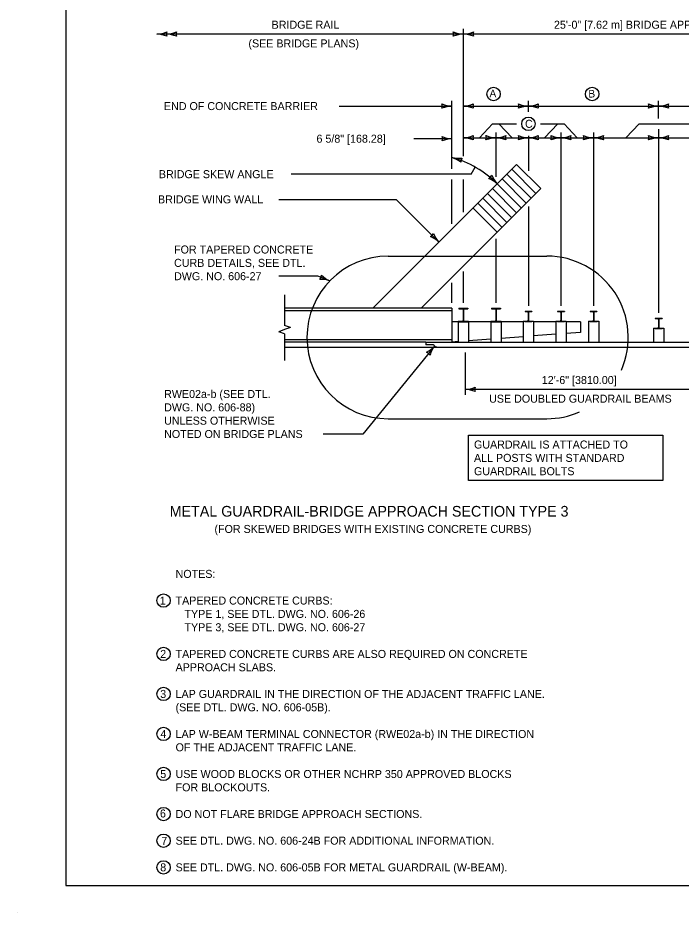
# Model space of a CAD drawing. Extents: x 49991.4 to 50021, y 49987.6 to 50011.4.
# Drawn here: x 49999.98 to 50004.95, y 49999.86 to 50006.57 of the extents above; entities that cross this region are included whole.
import ezdxf

# ---------------------------------------------------------------- set-up
doc = ezdxf.new("R2010")
doc.units = 0
for name, color, linetype in [('Level 1', 7, 'Continuous'), ('Level 2', 7, 'Continuous'), ('Level 3', 7, 'Continuous'), ('Level 4', 7, 'Continuous'), ('Level 6', 7, 'Continuous')]:
    doc.layers.add(name, color=color, linetype=linetype)

msp = doc.modelspace()

# ---------------------------------------------------------------- linework, layer by layer
at = {"layer": 'Level 1'}
for p, q in [((50002.638, 50004.3895), (50003.7157, 50005.4673)), ((50003.8609, 50005.2494), (50003.6793, 50005.431)), ((50003.8973, 50005.2857), (50003.7157, 50005.4673)), ((50003.7883, 50005.1768), (50003.6067, 50005.3583)), ((50003.8246, 50005.2131), (50003.643, 50005.3947)), ((50003.0012, 50004.3895), (50003.8973, 50005.2857)), ((50003.7157, 50005.1041), (50003.5341, 50005.2857)), ((50003.752, 50005.1404), (50003.5704, 50005.322)), ((50003.643, 50005.0315), (50003.4614, 50005.2131)), ((50003.6793, 50005.0678), (50003.4977, 50005.2494)), ((50003.5704, 50004.9588), (50003.3888, 50005.1404)), ((50003.6067, 50004.9952), (50003.4251, 50005.1767)), ((50003.2304, 50004.3895), (50001.9766, 50004.3895)), ((50003.2304, 50004.3705), (50001.9766, 50004.3705)), ((50003.2304, 50004.3895), (50003.2304, 50004.1359)), ((50003.2823, 50004.3909), (50003.3509, 50004.3909)), ((50003.2823, 50004.3909), (50003.2823, 50004.3857)), ((50003.2823, 50004.3857), (50003.3104, 50004.3857)), ((50003.315, 50004.3811), (50003.315, 50004.2965)), ((50003.3182, 50004.3811), (50003.3182, 50004.2965)), ((50003.3228, 50004.3857), (50003.3509, 50004.3857)), ((50003.3509, 50004.3909), (50003.3509, 50004.3857)), ((50003.5263, 50004.3909), (50003.5948, 50004.3909)), ((50003.5263, 50004.3909), (50003.5263, 50004.3857)), ((50003.5263, 50004.3857), (50003.5544, 50004.3857)), ((50003.5589, 50004.3811), (50003.5589, 50004.2965)), ((50003.5622, 50004.3811), (50003.5622, 50004.2965)), ((50003.5667, 50004.3857), (50003.5948, 50004.3857)), ((50003.5948, 50004.3909), (50003.5948, 50004.3857)), ((50003.7789, 50004.3673), (50003.8302, 50004.3673)), ((50003.7789, 50004.3673), (50003.7789, 50004.3645)), ((50003.7789, 50004.3645), (50003.7965, 50004.3645)), ((50003.8034, 50004.3575), (50003.8034, 50004.2989)), ((50003.8056, 50004.3575), (50003.8056, 50004.2989)), ((50003.8126, 50004.3645), (50003.8302, 50004.3645)), ((50003.8302, 50004.3673), (50003.8302, 50004.3645)), ((50004.0229, 50004.3673), (50004.0742, 50004.3673)), ((50004.0229, 50004.3673), (50004.0229, 50004.3645)), ((50004.0229, 50004.3645), (50004.0405, 50004.3645)), ((50004.0474, 50004.3575), (50004.0474, 50004.2989)), ((50004.0496, 50004.3575), (50004.0496, 50004.2989)), ((50004.0566, 50004.3645), (50004.0742, 50004.3645)), ((50004.0742, 50004.3673), (50004.0742, 50004.3645)), ((50004.2669, 50004.3673), (50004.3182, 50004.3673)), ((50004.2669, 50004.3673), (50004.2669, 50004.3645)), ((50004.2669, 50004.3645), (50004.2845, 50004.3645)), ((50004.2914, 50004.3575), (50004.2914, 50004.2989)), ((50004.2936, 50004.3575), (50004.2936, 50004.2989)), ((50004.3006, 50004.3645), (50004.3182, 50004.3645)), ((50004.3182, 50004.3673), (50004.3182, 50004.3645)), ((50003.2776, 50004.2868), (50003.2304, 50004.2868)), ((50003.2776, 50004.292), (50003.2817, 50004.292)), ((50003.2776, 50004.292), (50003.2776, 50004.1359)), ((50003.2817, 50004.2868), (50003.2817, 50004.292)), ((50003.2817, 50004.2868), (50003.2823, 50004.2868)), ((50003.2823, 50004.2868), (50003.2823, 50004.292)), ((50003.2823, 50004.292), (50003.3104, 50004.292)), ((50003.2823, 50004.2868), (50003.3509, 50004.2868)), ((50003.3228, 50004.292), (50003.3509, 50004.292)), ((50003.3509, 50004.2868), (50003.3509, 50004.292)), ((50003.3515, 50004.2868), (50003.3509, 50004.2868)), ((50003.3515, 50004.2868), (50003.3515, 50004.292)), ((50003.3515, 50004.292), (50003.3556, 50004.292)), ((50003.3556, 50004.292), (50003.3556, 50004.1359)), ((50003.5215, 50004.2868), (50003.3556, 50004.2868)), ((50003.5215, 50004.292), (50003.5256, 50004.292)), ((50003.5215, 50004.292), (50003.5215, 50004.1359)), ((50003.5256, 50004.2868), (50003.5256, 50004.292)), ((50003.5256, 50004.2868), (50003.5263, 50004.2868)), ((50003.5263, 50004.2868), (50003.5263, 50004.292)), ((50003.5263, 50004.292), (50003.5544, 50004.292)), ((50003.5263, 50004.2868), (50003.5948, 50004.2868)), ((50003.5667, 50004.292), (50003.5948, 50004.292)), ((50003.5948, 50004.2868), (50003.5948, 50004.292)), ((50003.5948, 50004.2868), (50003.5955, 50004.2868)), ((50003.5955, 50004.2868), (50003.5955, 50004.292)), ((50003.5955, 50004.292), (50003.5996, 50004.292)), ((50003.5996, 50004.292), (50003.5996, 50004.1359)), ((50003.7655, 50004.2868), (50003.5996, 50004.2868)), ((50003.7655, 50004.292), (50003.7783, 50004.292)), ((50003.7655, 50004.292), (50003.7655, 50004.1359)), ((50003.7783, 50004.2892), (50003.7783, 50004.292)), ((50003.7783, 50004.2892), (50003.7789, 50004.2892)), ((50003.7789, 50004.2892), (50003.7789, 50004.292)), ((50003.7789, 50004.292), (50003.7965, 50004.292)), ((50003.7789, 50004.2892), (50003.8302, 50004.2892)), ((50003.8126, 50004.292), (50003.8302, 50004.292)), ((50003.8302, 50004.2892), (50003.8302, 50004.292)), ((50003.8308, 50004.2892), (50003.8302, 50004.2892)), ((50003.8308, 50004.2892), (50003.8308, 50004.292)), ((50003.8308, 50004.292), (50003.8436, 50004.292)), ((50003.8436, 50004.292), (50003.8436, 50004.1359)), ((50004.0095, 50004.2868), (50003.8436, 50004.2868)), ((50004.0095, 50004.292), (50004.0222, 50004.292)), ((50004.0095, 50004.292), (50004.0095, 50004.1359)), ((50004.0222, 50004.2892), (50004.0222, 50004.292)), ((50004.0222, 50004.2892), (50004.0229, 50004.2892)), ((50004.0229, 50004.2892), (50004.0229, 50004.292)), ((50004.0229, 50004.292), (50004.0405, 50004.292)), ((50004.0229, 50004.2892), (50004.0742, 50004.2892)), ((50004.0566, 50004.292), (50004.0742, 50004.292)), ((50004.0742, 50004.2892), (50004.0742, 50004.292)), ((50004.0742, 50004.2892), (50004.0748, 50004.2892)), ((50004.0748, 50004.2892), (50004.0748, 50004.292)), ((50004.0748, 50004.292), (50004.0876, 50004.292)), ((50004.0876, 50004.292), (50004.0876, 50004.1359)), ((50004.1957, 50004.2868), (50004.0876, 50004.2868)), ((50004.1957, 50004.2868), (50004.1957, 50004.2074)), ((50004.2535, 50004.292), (50004.2535, 50004.1359)), ((50004.2535, 50004.292), (50004.2662, 50004.292)), ((50004.2662, 50004.2892), (50004.2662, 50004.292)), ((50004.2662, 50004.2892), (50004.3188, 50004.2892)), ((50004.2669, 50004.2892), (50004.2669, 50004.292)), ((50004.2669, 50004.292), (50004.2845, 50004.292)), ((50004.3006, 50004.292), (50004.3182, 50004.292)), ((50004.3182, 50004.2892), (50004.3182, 50004.292)), ((50004.3188, 50004.2892), (50004.3188, 50004.292)), ((50004.3188, 50004.292), (50004.3316, 50004.292)), ((50004.3316, 50004.292), (50004.3316, 50004.1359)), ((50004.7548, 50004.3152), (50004.8061, 50004.3152)), ((50004.7548, 50004.3152), (50004.7548, 50004.3124)), ((50004.7548, 50004.3124), (50004.7724, 50004.3124)), ((50004.7793, 50004.3054), (50004.7793, 50004.2469)), ((50004.7816, 50004.3054), (50004.7816, 50004.2469)), ((50004.7885, 50004.3124), (50004.8061, 50004.3124)), ((50004.8061, 50004.3152), (50004.8061, 50004.3124)), ((50004.1957, 50004.2074), (50004.0876, 50004.1994)), ((50004.7414, 50004.2399), (50004.7414, 50004.1359)), ((50004.7414, 50004.2399), (50004.7542, 50004.2399)), ((50004.7542, 50004.2371), (50004.7542, 50004.2399)), ((50004.7542, 50004.2371), (50004.8067, 50004.2371)), ((50004.7548, 50004.2371), (50004.7548, 50004.2399)), ((50004.7548, 50004.2399), (50004.7724, 50004.2399)), ((50004.7885, 50004.2399), (50004.8061, 50004.2399)), ((50004.8061, 50004.2371), (50004.8061, 50004.2399)), ((50004.8067, 50004.2371), (50004.8067, 50004.2399)), ((50004.8067, 50004.2399), (50004.8195, 50004.2399)), ((50004.8195, 50004.2399), (50004.8195, 50004.1359)), ((50003.2304, 50004.1511), (50001.9767, 50004.1511)), ((50003.0353, 50004.1359), (50001.9767, 50004.1359)), ((50003.0353, 50004.1359), (50003.0353, 50004.1156)), ((50003.0353, 50004.1359), (50007.507, 50004.1359)), ((50003.2776, 50004.1394), (50003.2304, 50004.1359)), ((50003.5215, 50004.1574), (50003.3556, 50004.1451)), ((50003.7655, 50004.1755), (50003.5996, 50004.1632)), ((50004.0095, 50004.1936), (50003.8436, 50004.1813)), ((50001.9767, 50004.0968), (50007.507, 50004.0968)), ((50003.0695, 50004.1156), (50003.0353, 50004.1156)), ((49999.9766, 49999.8624), (49999.9766, 49999.8624))]:
    msp.add_line(p, q, dxfattribs=at)
msp.add_lwpolyline([(50008.6146, 50011.2628), (50000.3356, 50011.2628), (50000.3356, 50000.0624), (50008.6146, 50000.0624)], close=True, dxfattribs=at)
for centre, radius, start, end in [((50003.3104, 50004.3811), 0.00455, 0, 90), ((50003.3228, 50004.3811), 0.00455, 90, 180), ((50003.5544, 50004.3811), 0.00455, 0, 90), ((50003.5667, 50004.3811), 0.00455, 90, 180), ((50003.7965, 50004.3575), 0.00696, 0, 90), ((50003.8126, 50004.3575), 0.00696, 90, 180), ((50004.0405, 50004.3575), 0.00696, 0, 90), ((50004.0566, 50004.3575), 0.00696, 90, 180), ((50004.2845, 50004.3575), 0.00696, 0, 90), ((50004.3006, 50004.3575), 0.00696, 90, 180), ((50003.3104, 50004.2965), 0.00455, 270, 0), ((50003.3228, 50004.2965), 0.00455, 180, 270), ((50003.5544, 50004.2965), 0.00455, 270, 0), ((50003.5667, 50004.2965), 0.00455, 180, 270), ((50003.7965, 50004.2989), 0.00696, 270, 0), ((50003.8126, 50004.2989), 0.00696, 180, 270), ((50004.0405, 50004.2989), 0.00696, 270, 0), ((50004.0566, 50004.2989), 0.00696, 180, 270), ((50004.2845, 50004.2989), 0.00696, 270, 0), ((50004.3006, 50004.2989), 0.00696, 180, 270), ((50004.7724, 50004.3054), 0.00696, 0, 90), ((50004.7885, 50004.3054), 0.00696, 90, 180), ((50004.7724, 50004.2469), 0.00696, 270, 0), ((50004.7885, 50004.2469), 0.00696, 180, 270)]:
    msp.add_arc(centre, radius, start, end, dxfattribs=at)
msp.add_spline([(50003.1175, 50004.0968), (50003.1118, 50004.0985), (50003.1058, 50004.1026), (50003.1007, 50004.1085), (50003.0968, 50004.1125), (50003.0876, 50004.1146), (50003.0695, 50004.1156)], degree=3, dxfattribs=at)
at = {"layer": 'Level 2'}
msp.add_lwpolyline([(50003.3561, 50003.4373), (50004.8112, 50003.4373), (50004.8112, 50003.0973), (50003.3561, 50003.0973)], close=True, dxfattribs=at)
for centre, radius in [((50003.5429, 50005.995), 0.0504), ((50004.2824, 50005.995), 0.0504), ((50003.8043, 50005.7717), 0.0505), ((50001.0689, 50002.1978), 0.05), ((50001.0689, 50001.7978), 0.05), ((50001.0689, 50001.4978), 0.05), ((50001.0689, 50001.1978), 0.05), ((50001.0689, 50000.8978), 0.05), ((50001.0689, 50000.5978), 0.05), ((50001.0689, 50000.3978), 0.05), ((50001.0689, 50000.1978), 0.05)]:
    msp.add_circle(centre, radius, dxfattribs=at)
at = {"layer": 'Level 3'}
for p, q in [((50003.3166, 50005.5298), (50003.3166, 50006.4845)), ((50003.3166, 50006.4445), (50001.0189, 50006.4445)), ((50007.2182, 50006.4445), (50003.3166, 50006.4445)), ((50003.2304, 50005.4342), (50003.2304, 50005.9446)), ((50003.8043, 50005.8622), (50003.8043, 50005.9446)), ((50004.7798, 50005.8117), (50004.7798, 50005.9446)), ((50002.3862, 50005.9046), (50003.2304, 50005.9046)), ((50003.3166, 50005.9046), (50003.8043, 50005.9046)), ((50003.8043, 50005.9046), (50004.7798, 50005.9046)), ((50004.7798, 50005.9046), (50007.2182, 50005.9046)), ((50003.536, 50005.7717), (50003.4377, 50005.6672)), ((50003.536, 50005.7717), (50003.7138, 50005.7717)), ((50003.5833, 50005.7717), (50003.6816, 50005.6672)), ((50003.8947, 50005.7717), (50004.0716, 50005.7717)), ((50004.0243, 50005.7717), (50003.926, 50005.6672)), ((50004.0716, 50005.7717), (50004.1698, 50005.6672)), ((50004.634, 50005.7717), (50004.5358, 50005.6672)), ((50004.634, 50005.7717), (50005.6646, 50005.7717)), ((50003.5604, 50005.7072), (50003.5604, 50005.3736)), ((50003.8043, 50005.6813), (50003.8043, 50005.4187)), ((50004.0481, 50005.7072), (50004.0481, 50004.4073)), ((50004.292, 50005.7072), (50004.292, 50004.4073)), ((50004.7797, 50005.7317), (50004.7797, 50004.3552)), ((50003.2304, 50005.66), (50002.9452, 50005.66)), ((50003.3166, 50005.6672), (50003.5604, 50005.6672)), ((50003.5604, 50005.6672), (50003.8043, 50005.6672)), ((50003.8043, 50005.6672), (50004.0481, 50005.6672)), ((50004.0481, 50005.6672), (50004.292, 50005.6672)), ((50004.292, 50005.6672), (50004.7797, 50005.6672)), ((50004.7797, 50005.6672), (50005.2673, 50005.6672)), ((50003.3761, 50005.3942), (50003.4058, 50005.4468)), ((50003.3761, 50005.3942), (50002.0257, 50005.3942)), ((50003.2304, 50005.022), (50003.2304, 50005.3542)), ((50003.3166, 50005.1082), (50003.3166, 50005.3542)), ((50001.9329, 50005.2052), (50002.8136, 50005.2052)), ((50002.8136, 50005.2052), (50003.1336, 50004.8852)), ((50003.8043, 50005.1527), (50003.8043, 50004.4073)), ((50003.5604, 50004.9089), (50003.5604, 50004.4309)), ((50002.2247, 50004.6294), (50001.9329, 50004.6294)), ((50002.3162, 50004.5949), (50002.2247, 50004.6294)), ((50003.3166, 50004.4309), (50003.3166, 50004.665)), ((50003.2304, 50004.4295), (50003.2304, 50004.5788)), ((50003.1016, 50004.1075), (50002.5618, 50003.4463)), ((50003.3313, 50004.0568), (50003.3313, 50003.7411)), ((50005.2821, 50003.7811), (50003.3313, 50003.7811)), ((50002.5618, 50003.4463), (50002.2657, 50003.4463))]:
    msp.add_line(p, q, dxfattribs=at)
for centre, radius, start, end in [((50001.0077, 50006.6715), 0.2273, 272.82731, 292.07716), ((50001.01, 50006.2279), 0.2168, 67.45601, 87.63952), ((50001.144, 50006.4445), 0.0534, 162.13882, 197.86118), ((50001.0793, 50006.6715), 0.2273, 272.82731, 292.07716), ((50001.0816, 50006.2279), 0.2168, 67.45601, 87.63952), ((50001.2156, 50006.4445), 0.0534, 162.13882, 197.86118), ((50003.3257, 50006.6667), 0.2223, 247.45601, 267.63952), ((50003.1884, 50006.4445), 0.0548, 342.13882, 17.86118), ((50003.3281, 50006.2118), 0.233, 92.82731, 112.07716), ((50003.3051, 50006.6772), 0.233, 272.82731, 292.07716), ((50003.3074, 50006.2224), 0.2223, 67.45601, 87.63952), ((50003.4448, 50006.4445), 0.0548, 162.13882, 197.86118), ((50003.2394, 50006.1212), 0.2168, 247.45601, 267.63952), ((50003.1054, 50005.9046), 0.0534, 342.13882, 17.86118), ((50003.2416, 50005.6776), 0.2273, 92.82731, 112.07716), ((50003.3054, 50006.1316), 0.2273, 272.82731, 292.07716), ((50003.3077, 50005.6879), 0.2168, 67.45601, 87.63952), ((50003.4416, 50005.9046), 0.0534, 162.13882, 197.86118), ((50003.8132, 50006.1212), 0.2168, 247.45601, 267.63952), ((50003.6792, 50005.9046), 0.0534, 342.13882, 17.86118), ((50003.8155, 50005.6776), 0.2273, 92.82731, 112.07716), ((50003.7931, 50006.1316), 0.2273, 272.82731, 292.07716), ((50003.7953, 50005.6879), 0.2168, 67.45601, 87.63952), ((50003.9293, 50005.9046), 0.0534, 162.13882, 197.86118), ((50004.7887, 50006.1212), 0.2168, 247.45601, 267.63952), ((50004.6547, 50005.9046), 0.0534, 342.13882, 17.86118), ((50004.791, 50005.6776), 0.2273, 92.82731, 112.07716), ((50004.7686, 50006.1316), 0.2273, 272.82731, 292.07716), ((50004.7708, 50005.6879), 0.2168, 67.45601, 87.63952), ((50004.9048, 50005.9046), 0.0534, 162.13882, 197.86118), ((50003.2391, 50005.8711), 0.2113, 247.45601, 267.63952), ((50003.1086, 50005.66), 0.0521, 342.13882, 17.86118), ((50003.3054, 50005.8942), 0.2273, 272.82731, 292.07716), ((50003.4416, 50005.6672), 0.0534, 162.13882, 197.86118), ((50003.5694, 50005.8839), 0.2168, 247.45601, 267.63952), ((50003.4354, 50005.6672), 0.0534, 342.13882, 17.86118), ((50003.5492, 50005.8942), 0.2273, 272.82731, 292.07716), ((50003.6855, 50005.6672), 0.0534, 162.13882, 197.86118), ((50003.8132, 50005.8839), 0.2168, 247.45601, 267.63952), ((50003.6792, 50005.6672), 0.0534, 342.13882, 17.86118), ((50003.7931, 50005.8942), 0.2273, 272.82731, 292.07716), ((50003.9293, 50005.6672), 0.0534, 162.13882, 197.86118), ((50004.0571, 50005.8839), 0.2168, 247.45601, 267.63952), ((50003.9231, 50005.6672), 0.0534, 342.13882, 17.86118), ((50004.0369, 50005.8942), 0.2273, 272.82731, 292.07716), ((50004.1732, 50005.6672), 0.0534, 162.13882, 197.86118), ((50004.3009, 50005.8839), 0.2168, 247.45601, 267.63952), ((50004.1669, 50005.6672), 0.0534, 342.13882, 17.86118), ((50004.2808, 50005.8942), 0.2273, 272.82731, 292.07716), ((50004.417, 50005.6672), 0.0534, 162.13882, 197.86118), ((50004.7886, 50005.8839), 0.2168, 247.45601, 267.63952), ((50004.6546, 50005.6672), 0.0534, 342.13882, 17.86118), ((50004.7684, 50005.8942), 0.2273, 272.82731, 292.07716), ((50004.9047, 50005.6672), 0.0534, 162.13882, 197.86118), ((50003.2414, 50005.4388), 0.2214, 92.82731, 112.07716), ((50003.3077, 50005.4506), 0.2168, 67.45601, 87.63952), ((50003.5716, 50005.4403), 0.2273, 92.82731, 112.07716), ((50003.5515, 50005.4506), 0.2168, 67.45601, 87.63952), ((50003.8155, 50005.4403), 0.2273, 92.82731, 112.07716), ((50003.7953, 50005.4506), 0.2168, 67.45601, 87.63952), ((50004.0593, 50005.4403), 0.2273, 92.82731, 112.07716), ((50004.0392, 50005.4506), 0.2168, 67.45601, 87.63952), ((50004.3032, 50005.4403), 0.2273, 92.82731, 112.07716), ((50004.283, 50005.4506), 0.2168, 67.45601, 87.63952), ((50004.7909, 50005.4403), 0.2273, 92.82731, 112.07716), ((50004.7707, 50005.4506), 0.2168, 67.45601, 87.63952), ((50003.029, 50004.7788), 0.767, 45.09469, 74.7701), ((50003.1649, 50005.3121), 0.2168, 52.22611, 72.40962), ((50003.2792, 50005.7408), 0.2273, 257.59741, 276.84726), ((50003.3511, 50005.486), 0.0534, 146.90892, 182.63128), ((50003.4818, 50005.4103), 0.0534, 297.23351, 332.95587), ((50003.4181, 50005.1533), 0.2273, 47.922, 67.17185), ((50003.7297, 50005.4692), 0.2168, 202.5507, 222.73421), ((50003.0452, 50004.9736), 0.0534, 297.14169, 332.86405), ((50003.2931, 50005.0321), 0.2168, 202.45888, 222.64239), ((50002.981, 50004.7168), 0.2273, 47.83018, 67.08003), ((50002.1993, 50004.6391), 0.0534, 321.39597, 357.11833), ((50002.2463, 50004.3788), 0.2271, 72.08446, 91.33431), ((50002.4012, 50004.7942), 0.2167, 226.71316, 246.89667), ((50002.9353, 50004.2551), 0.2223, 298.22822, 318.41173), ((50003.2892, 50003.9692), 0.233, 143.59952, 162.84937), ((50003.0205, 50004.0082), 0.0548, 32.91103, 68.63339), ((50003.3201, 50004.0081), 0.2273, 272.82731, 292.07716), ((50003.3224, 50003.5644), 0.2168, 67.45601, 87.63952), ((50003.4564, 50003.7811), 0.0534, 162.13882, 197.86118)]:
    msp.add_arc(centre, radius, start, end, dxfattribs=at)
at = {"layer": 'Level 4'}
for p, q in [((50002.7537, 50004.7798), (50003.9433, 50004.7798)), ((50002.7537, 50003.5606), (50003.9433, 50003.5606))]:
    msp.add_line(p, q, dxfattribs=at)
for centre, start, end in [((50002.7537, 50004.1704), 90, 270), ((50003.9432, 50004.1703), 336.29665, 90), ((50003.9432, 50004.1703), 270, 293.5679)]:
    msp.add_arc(centre, 0.6096, start, end, dxfattribs=at)
at = {"layer": 'Level 6'}
for p, q in [((50001.9766, 50004.4895), (50001.9766, 50004.2609)), ((50001.9767, 50004.2292), (50001.9321, 50004.2134)), ((50001.9767, 50004.1976), (50001.9321, 50004.2134)), ((50002.0212, 50004.245), (50001.9766, 50004.2609)), ((50002.0212, 50004.245), (50001.9767, 50004.2292)), ((50001.9767, 50004.1976), (50001.9767, 50003.9968))]:
    msp.add_line(p, q, dxfattribs=at)

# ---------------------------------------------------------------- texts
at = {"layer": 'Level 2'}
for s, height, p in [('25\'-0" [7.62 m] BRIDGE APPROACH SECTION PAY LIMITS', 0.06, (50003.9958, 50006.4845)), ('BRIDGE RAIL', 0.06, (50001.8789, 50006.4845)), ('(SEE BRIDGE PLANS)', 0.06, (50001.7051, 50006.3445)), ('A', 0.057, (50003.5124, 50005.9701)), ('B', 0.057, (50004.2537, 50005.9688)), ('END OF CONCRETE BARRIER', 0.06, (50001.0716, 50005.8746)), ('C', 0.06, (50003.7788, 50005.7417)), ('6 5/8" [168.28]', 0.06, (50002.2154, 50005.63)), ('BRIDGE SKEW ANGLE', 0.06, (50001.0336, 50005.3642)), ('BRIDGE WING WALL', 0.06, (50001.027, 50005.1752)), ('FOR TAPERED CONCRETE ', 0.06, (50001.1476, 50004.7994)), ('CURB DETAILS, SEE DTL.', 0.06, (50001.1476, 50004.6994)), ('DWG. NO. 606-27', 0.06, (50001.1476, 50004.5994)), ('12\'-6" [3810.00]', 0.06, (50003.9046, 50003.8211)), ('RWE02a-b (SEE DTL.', 0.06, (50001.073, 50003.7163)), ('USE DOUBLED GUARDRAIL BEAMS', 0.06, (50003.5097, 50003.6811)), ('DWG. NO. 606-88)', 0.06, (50001.073, 50003.6163)), ('UNLESS OTHERWISE', 0.06, (50001.073, 50003.5163)), ('NOTED ON BRIDGE PLANS', 0.06, (50001.073, 50003.4163)), ('GUARDRAIL IS ATTACHED TO ', 0.06, (50003.3961, 50003.3374)), ('ALL POSTS WITH STANDARD', 0.06, (50003.3961, 50003.2374)), ('GUARDRAIL BOLTS', 0.06, (50003.3961, 50003.1374)), ('METAL GUARDRAIL-BRIDGE APPROACH SECTION TYPE 3', 0.08, (50001.1148, 50002.8272)), ('(FOR SKEWED BRIDGES WITH EXISTING CONCRETE CURBS)', 0.06, (50001.4505, 50002.7047)), ('NOTES:', 0.06, (50001.1589, 50002.3678)), ('1', 0.06, (50001.0406, 50002.1678)), ('TAPERED CONCRETE CURBS:', 0.06, (50001.1589, 50002.1678)), ('   TYPE 1, SEE DTL. DWG. NO. 606-26', 0.06, (50001.1589, 50002.0678)), ('   TYPE 3, SEE DTL. DWG. NO. 606-27', 0.06, (50001.1589, 50001.9678)), ('2', 0.06, (50001.0437, 50001.7678)), ('TAPERED CONCRETE CURBS ARE ALSO REQUIRED ON CONCRETE ', 0.06, (50001.1589, 50001.7678)), ('APPROACH SLABS.', 0.06, (50001.1589, 50001.6678)), ('3', 0.06, (50001.0437, 50001.4678)), ('LAP GUARDRAIL IN THE DIRECTION OF THE ADJACENT TRAFFIC LANE.', 0.06, (50001.1589, 50001.4678)), ('(SEE DTL. DWG. NO. 606-05B).', 0.06, (50001.1589, 50001.3678)), ('4', 0.06, (50001.0449, 50001.1678)), ('LAP W-BEAM TERMINAL CONNECTOR (RWE02a-b) IN THE DIRECTION', 0.06, (50001.1589, 50001.1678)), ('OF THE ADJACENT TRAFFIC LANE.', 0.06, (50001.1589, 50001.0678)), ('5', 0.06, (50001.044, 50000.8678)), ('USE WOOD BLOCKS OR OTHER NCHRP 350 APPROVED BLOCKS ', 0.06, (50001.1589, 50000.8678)), ('FOR BLOCKOUTS.', 0.06, (50001.1589, 50000.7678)), ('6', 0.06, (50001.0417, 50000.5718)), ('DO NOT FLARE BRIDGE APPROACH SECTIONS.', 0.06, (50001.1589, 50000.5678)), ('7', 0.06, (50001.0521, 50000.3666)), ('SEE DTL. DWG. NO. 606-24B FOR ADDITIONAL INFORMATION.', 0.06, (50001.1589, 50000.3678)), ('8', 0.06, (50001.0439, 50000.1678)), ('SEE DTL. DWG. NO. 606-05B FOR METAL GUARDRAIL (W-BEAM).', 0.06, (50001.1589, 50000.1678))]:
    msp.add_text(s, height=height, dxfattribs=at).set_placement(p)

doc.saveas('drawing.dxf')
